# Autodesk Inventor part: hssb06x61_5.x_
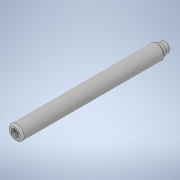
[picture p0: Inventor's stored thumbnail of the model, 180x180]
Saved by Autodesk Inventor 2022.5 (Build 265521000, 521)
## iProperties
Created: 2021-02
Part Number: hssb06x61_5.x_
Material: 一般
Document SubType Name: Modeling
Designer: ImaoCorp
Density: 1 g/cm^3
Appearance: 既定
Sending System: SOLIDWORKS 2019-2019304
MC: AMD64
MC_MODEL: Intel64 Family 6 Model 60 Stepping 3, GenuineIntel
OS: Windows_NT
FRU: Parasolid Version 31.0, build 290,  9- 1-2019
FORMAT: text
GUISE: transmit
KEY: hssb06x61_5
FILE: hssb06x61_5.x_t
DATE: Mon Feb 22 14:59:38 2021
Author: ImaoCorp
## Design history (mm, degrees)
feature "Base1"
node "ソリッド1"
